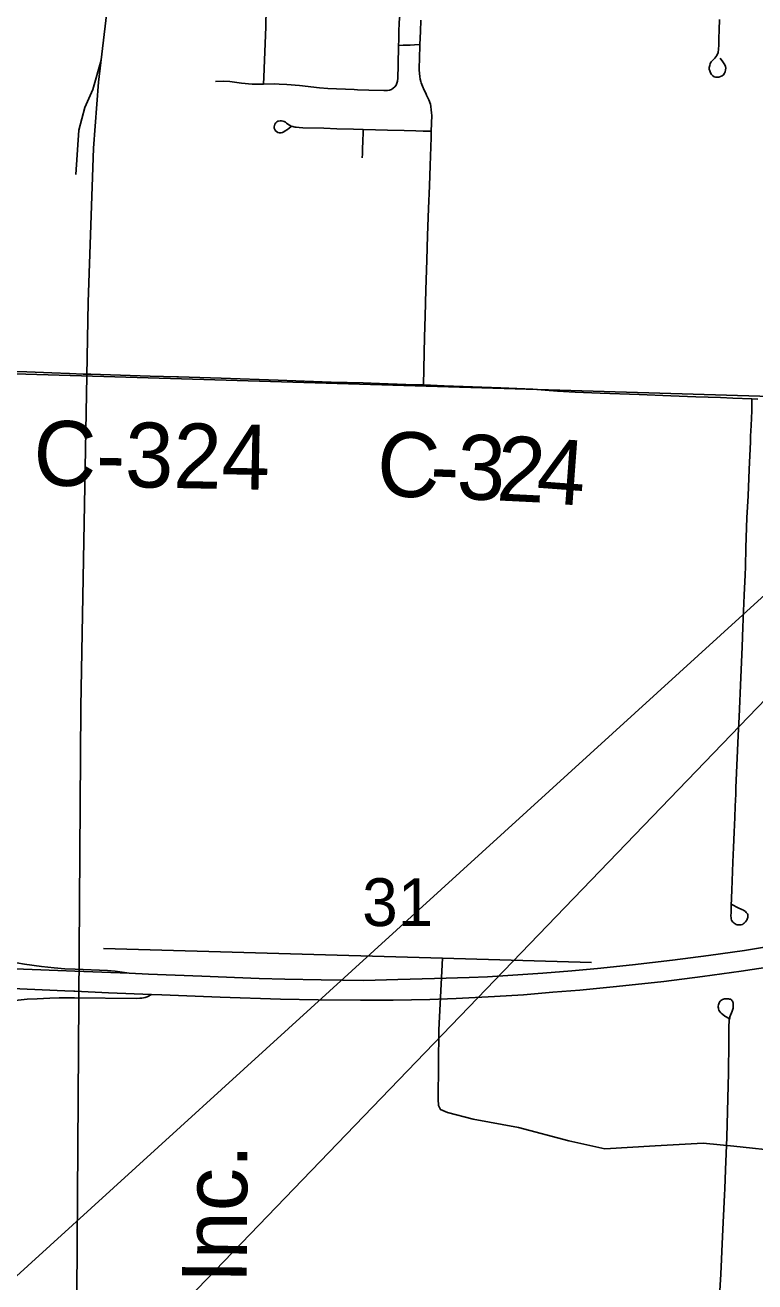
# Model space of a CAD drawing. Extents: x -59 to 43, y 0 to 22.
# Drawn here: x 25.359 to 25.998, y 15.494 to 16.594 of the extents above; entities that cross this region are included whole.
import ezdxf

# ---------------------------------------------------------------- set-up
doc = ezdxf.new("R2010")
doc.units = 0
for name, color, linetype in [('BR_P_Gen_Text', 7, 'Continuous'), ('GM_X_City_Street', 7, 'Continuous'), ('GM_X_County_Road', 7, 'Continuous'), ('GM_X_County_Road_Text', 7, 'Continuous'), ('GM_X_Interchange_Ramps', 7, 'Continuous'), ('GM_X_Minor_River', 7, 'Continuous'), ('GM_X_Rail_Line', 7, 'Continuous'), ('GM_X_Rail_Line_Text', 7, 'Continuous'), ('GM_X_Section', 7, 'Continuous'), ('GM_X_Section_Text', 7, 'Continuous'), ('GM_X_Township_Road', 7, 'Continuous'), ('GM_X_US_Route', 7, 'Continuous')]:
    doc.layers.add(name, color=color, linetype=linetype)

msp = doc.modelspace()

# ---------------------------------------------------------------- linework, layer by layer
at = {"layer": 'BR_P_Gen_Text'}
msp.add_lwpolyline([(26.7273, 16.7521), (23.5585, 13.8664), (23.9482, 13.8664)], close=True, dxfattribs=at)
at = {"layer": 'GM_X_City_Street'}
for points in [[(25.5677, 16.5426), (25.568, 16.5486), (25.5687, 16.5635), (25.5699, 16.5926), (25.5703, 16.6087), (25.5706, 16.6155), (25.5708, 16.6208)], [(25.5708, 16.6208), (25.5869, 16.6207), (25.5925, 16.6209), (25.6242, 16.6204), (25.6527, 16.6191), (25.6788, 16.6177), (25.6813, 16.6173), (25.6831, 16.6168), (25.6847, 16.6159), (25.6861, 16.6147), (25.6869, 16.6138), (25.6876, 16.6121), (25.6879, 16.6102), (25.6878, 16.6077), (25.6867, 16.5966), (25.6862, 16.5879), (25.6862, 16.581), (25.686, 16.5764)], [(25.7078, 16.2791), (25.7089, 16.321), (25.7093, 16.3394), (25.7099, 16.3623), (25.7108, 16.3884), (25.7114, 16.4101), (25.7124, 16.4336), (25.7132, 16.4534), (25.7138, 16.4714), (25.7145, 16.4957), (25.7147, 16.5012), (25.7151, 16.5149), (25.715, 16.5173), (25.7147, 16.52), (25.7144, 16.5228), (25.7139, 16.525), (25.7126, 16.5287), (25.7115, 16.5312), (25.7106, 16.5328), (25.7098, 16.5345), (25.7084, 16.5373), (25.7069, 16.5407), (25.7058, 16.5437), (25.7055, 16.5449), (25.705, 16.5468), (25.7046, 16.5493), (25.7043, 16.5518), (25.7042, 16.555), (25.7045, 16.5668), (25.7047, 16.5749), (25.7048, 16.5771), (25.7053, 16.5886), (25.7056, 16.5985)], [(25.9677, 16.5653), (25.97, 16.5621), (25.9717, 16.5593), (25.9723, 16.5578), (25.9725, 16.5564), (25.9723, 16.5549), (25.972, 16.5534), (25.9715, 16.5521), (25.9705, 16.5507), (25.9694, 16.5499), (25.968, 16.5491), (25.9664, 16.5486), (25.965, 16.5485), (25.9636, 16.5486), (25.9622, 16.549), (25.9611, 16.5499), (25.96, 16.551), (25.9591, 16.5524), (25.9584, 16.5541), (25.9581, 16.5556), (25.9581, 16.5571), (25.9584, 16.5588), (25.9588, 16.5606), (25.9597, 16.5619), (25.9606, 16.563), (25.9622, 16.5645), (25.963, 16.5653), (25.9638, 16.5663), (25.9648, 16.5677), (25.9658, 16.5702), (25.966, 16.5732), (25.9663, 16.5766), (25.9665, 16.5823), (25.9667, 16.59), (25.967, 16.5992)], [(25.5677, 16.5426), (25.5779, 16.5427), (25.5816, 16.5426), (25.5884, 16.5421), (25.5995, 16.5412), (25.6168, 16.5393), (25.6242, 16.5387), (25.6471, 16.5377), (25.6502, 16.5376), (25.6601, 16.5373), (25.6732, 16.5368), (25.6763, 16.5369), (25.6781, 16.5373), (25.6798, 16.5379), (25.6814, 16.5389), (25.6828, 16.5401), (25.6839, 16.5416), (25.6846, 16.5433), (25.6851, 16.5451), (25.6853, 16.5476), (25.6858, 16.5592), (25.686, 16.5764)], [(25.686, 16.5764), (25.69, 16.5766), (25.6923, 16.5766), (25.6963, 16.5767), (25.7, 16.5769), (25.7048, 16.5771)], [(25.5259, 16.5448), (25.5327, 16.545), (25.5383, 16.5447), (25.5487, 16.5434), (25.558, 16.5426), (25.5611, 16.5425), (25.5677, 16.5426)], [(25.5921, 16.5054), (25.5902, 16.504), (25.5888, 16.5029), (25.5869, 16.5015), (25.5856, 16.5007), (25.5845, 16.5002), (25.5833, 16.4999), (25.5821, 16.4998), (25.5815, 16.4999), (25.5803, 16.5002), (25.5792, 16.5009), (25.5787, 16.5013), (25.578, 16.5022), (25.5777, 16.5028), (25.5773, 16.504), (25.5772, 16.5052), (25.5774, 16.5064), (25.5778, 16.5075), (25.5785, 16.5085), (25.5794, 16.5094), (25.5805, 16.51), (25.5811, 16.5102), (25.5823, 16.5104), (25.5835, 16.5104), (25.5848, 16.5102), (25.5859, 16.5097), (25.587, 16.5091), (25.588, 16.5084), (25.59, 16.5069), (25.5911, 16.5063), (25.5922, 16.5058), (25.5934, 16.5054), (25.5945, 16.505), (25.5955, 16.5048), (25.5965, 16.5047), (25.599, 16.5045), (25.6023, 16.5043), (25.6208, 16.5038), (25.6319, 16.5035), (25.6465, 16.5031), (25.6551, 16.5029), (25.6658, 16.5026), (25.6763, 16.5023), (25.691, 16.5019), (25.7012, 16.5016), (25.7076, 16.5014), (25.7147, 16.5012)], [(25.6543, 16.478), (25.6544, 16.4816), (25.6545, 16.4852), (25.6548, 16.4931), (25.655, 16.4995), (25.6551, 16.5029)]]:
    msp.add_lwpolyline(points, dxfattribs=at)
at = {"layer": 'GM_X_County_Road'}
msp.add_line((25.9954, 16.2669), (26.0005, 16.2667), dxfattribs=at)
for points in [[(25.3268, 16.2917), (25.3358, 16.2915), (25.3513, 16.2908), (25.3606, 16.2905), (25.3825, 16.2897), (25.3981, 16.2891), (25.4099, 16.2886)], [(25.4099, 16.2886), (25.4123, 16.2886), (25.4157, 16.2885), (25.4166, 16.2885)], [(25.4166, 16.2885), (25.4251, 16.2883), (25.4686, 16.2869), (25.4919, 16.2863), (25.4927, 16.2862)], [(25.4927, 16.2862), (25.4935, 16.2862), (25.5308, 16.285), (25.5806, 16.2834), (25.6272, 16.2817), (25.6552, 16.2809), (25.6693, 16.2803)], [(25.6693, 16.2803), (25.6925, 16.2794), (25.7078, 16.2791)], [(25.7078, 16.2791), (25.726, 16.2784), (25.7508, 16.2774), (25.7757, 16.2766), (25.8036, 16.2754), (25.8252, 16.2738), (25.8407, 16.2728), (25.8625, 16.2719), (25.8966, 16.2707), (25.9245, 16.2697), (25.9463, 16.2688), (25.968, 16.2681), (25.9787, 16.2677), (25.9954, 16.2669)]]:
    msp.add_lwpolyline(points, dxfattribs=at)
at = {"layer": 'GM_X_Interchange_Ramps'}
for points in [[(25.403, 15.7676), (25.394, 15.768), (25.3847, 15.7687), (25.3735, 15.7699), (25.3587, 15.7721), (25.3519, 15.7732), (25.3447, 15.7745), (25.3313, 15.7774), (25.3192, 15.7804), (25.2976, 15.7862), (25.2598, 15.7967), (25.2166, 15.8085), (25.2017, 15.8126), (25.1893, 15.816), (25.1864, 15.8168), (25.1842, 15.8171), (25.1817, 15.8174), (25.1772, 15.8175)], [(25.4502, 15.7641), (25.4379, 15.7658), (25.4313, 15.7664), (25.403, 15.7676)], [(25.4024, 15.7425), (25.4564, 15.7421), (25.4597, 15.7422), (25.4612, 15.7423), (25.4629, 15.7426), (25.4644, 15.743), (25.4659, 15.7435), (25.4698, 15.7454)], [(25.175, 15.7029), (25.1761, 15.7029), (25.1798, 15.703), (25.1847, 15.7038), (25.1914, 15.7052), (25.212, 15.7101), (25.2357, 15.7154), (25.2587, 15.7208), (25.2859, 15.7273), (25.3108, 15.7331), (25.3272, 15.7365), (25.3413, 15.739), (25.3505, 15.7403), (25.3611, 15.7414), (25.3697, 15.7418), (25.3808, 15.7423), (25.389, 15.7426), (25.4024, 15.7425)]]:
    msp.add_lwpolyline(points, dxfattribs=at)
at = {"layer": 'GM_X_Minor_River'}
for points in [[(25.8549, 15.7735), (25.7244, 15.7773), (25.4277, 15.7858)], [(26.0665, 15.6035), (25.9796, 15.6128), (25.9527, 15.6152), (25.9106, 15.613), (25.8666, 15.6105), (25.8351, 15.6174), (25.7911, 15.629), (25.7513, 15.6363), (25.7289, 15.6421), (25.7229, 15.6447), (25.721, 15.6482), (25.7206, 15.6539), (25.7212, 15.7146), (25.7244, 15.7773)]]:
    msp.add_lwpolyline(points, dxfattribs=at)
at = {"layer": 'GM_X_Rail_Line'}
for points in [[(25.3948, 14.1), (25.3961, 14.2211), (25.3988, 14.6701), (25.4079, 15.9972), (25.4144, 16.3516), (25.419, 16.4865), (25.4235, 16.5443), (25.4371, 16.6599), (25.4762, 17.0572), (25.4837, 17.1373), (25.4914, 17.219), (25.4936, 17.2735), (25.4946, 17.3274), (25.4973, 17.5422), (25.5003, 17.9438), (25.5067, 18.4239), (25.5079, 18.556), (25.5143, 18.6352), (25.5252, 18.7035), (25.5418, 18.7744), (25.5673, 18.8657), (25.6145, 19.001)], [(25.4037, 16.4635), (25.4063, 16.5022), (25.4115, 16.5219), (25.4185, 16.5378), (25.4258, 16.5635)]]:
    msp.add_lwpolyline(points, dxfattribs=at)
at = {"layer": 'GM_X_Section'}
for points in [[(25.1878, 17.2935), (26.2782, 17.275), (26.2361, 16.2622), (25.1744, 16.294), (25.173, 16.308)], [(25.1744, 16.294), (26.2361, 16.2622), (26.1685, 15.2661), (25.1667, 15.3001)]]:
    msp.add_lwpolyline(points, close=True, dxfattribs=at)
at = {"layer": 'GM_X_Township_Road'}
for points in [[(25.9777, 15.8242), (25.9834, 15.8214), (25.9865, 15.82), (25.9874, 15.8196), (25.9882, 15.8191), (25.989, 15.8186), (25.9897, 15.818), (25.9904, 15.8174), (25.991, 15.8167), (25.9914, 15.816), (25.9917, 15.8154), (25.9919, 15.8146), (25.9919, 15.814), (25.9918, 15.8129), (25.9916, 15.8122), (25.9912, 15.8114), (25.9909, 15.8107), (25.9904, 15.8099), (25.9899, 15.8092), (25.9893, 15.8085), (25.9886, 15.8079), (25.9878, 15.8074), (25.987, 15.8069), (25.9861, 15.8066), (25.9852, 15.8065), (25.9842, 15.8064), (25.9833, 15.8065), (25.9824, 15.8066), (25.9815, 15.8069), (25.9806, 15.8073), (25.9799, 15.8078), (25.9792, 15.8084), (25.9785, 15.8091), (25.978, 15.8098), (25.9776, 15.8107), (25.9773, 15.8116), (25.9771, 15.8125), (25.977, 15.8143), (25.9771, 15.8174), (25.9773, 15.823), (25.9777, 15.8367), (25.9787, 15.8612), (25.9792, 15.8742), (25.9798, 15.8876), (25.9803, 15.9004), (25.9807, 15.9105), (25.9812, 15.9208), (25.9814, 15.9263), (25.9834, 15.9722), (25.9841, 15.9886), (25.9856, 16.0231), (25.9867, 16.0498), (25.9874, 16.0672), (25.9886, 16.0952), (25.9895, 16.1128), (25.9898, 16.12), (25.9901, 16.1368), (25.991, 16.1629), (25.992, 16.1821), (25.993, 16.2051), (25.994, 16.2293), (25.9942, 16.2343), (25.9946, 16.2436), (25.9952, 16.2566), (25.9953, 16.2622), (25.9954, 16.2669)], [(25.9671, 15.4814), (25.9681, 15.5007), (25.9696, 15.5336), (25.9714, 15.5702), (25.9716, 15.5752), (25.9722, 15.5919), (25.9734, 15.6205), (25.975, 15.677), (25.975, 15.6851), (25.9751, 15.6956), (25.9753, 15.7087), (25.9753, 15.718), (25.9755, 15.7217), (25.9756, 15.7232), (25.9757, 15.7241), (25.9759, 15.725), (25.9761, 15.7258), (25.9782, 15.731), (25.9789, 15.7334), (25.9791, 15.735), (25.9791, 15.7362), (25.9791, 15.7372), (25.9789, 15.7381), (25.9787, 15.7388), (25.9783, 15.7395), (25.9779, 15.7402), (25.9775, 15.7407), (25.9765, 15.7413), (25.9758, 15.7415), (25.975, 15.7417), (25.9742, 15.7418), (25.9733, 15.7418), (25.9724, 15.7417), (25.9714, 15.7416), (25.9706, 15.7414), (25.9697, 15.7411), (25.9688, 15.7406), (25.9683, 15.7401), (25.9677, 15.7396), (25.9671, 15.7389), (25.9666, 15.7381), (25.9663, 15.7373), (25.966, 15.7363), (25.9659, 15.7354), (25.9659, 15.7345), (25.966, 15.7336), (25.9662, 15.7328), (25.9665, 15.7319), (25.967, 15.731), (25.9677, 15.7301), (25.9686, 15.729), (25.9698, 15.7279), (25.9718, 15.7266), (25.9755, 15.7245)]]:
    msp.add_lwpolyline(points, dxfattribs=at)
at = {"layer": 'GM_X_US_Route'}
for points in [[(25.4028, 15.7659), (25.4262, 15.7651), (25.4502, 15.7641), (25.4672, 15.7634), (25.5138, 15.7615), (25.5641, 15.7595), (25.5864, 15.7589), (25.6183, 15.7584), (25.6558, 15.7578), (25.6853, 15.7587), (25.7176, 15.7595), (25.748, 15.7603), (25.7638, 15.7609), (25.7861, 15.7625), (25.8124, 15.7641), (25.8378, 15.7661), (25.8601, 15.7682), (25.8907, 15.7715), (25.9259, 15.7755), (25.9574, 15.7796), (25.9888, 15.7841), (26.0225, 15.7895)], [(25.1713, 15.7747), (25.1756, 15.7745), (25.1789, 15.7744), (25.2398, 15.7722), (25.3429, 15.7682), (25.3877, 15.7664), (25.4028, 15.7659)], [(25.4017, 15.7484), (25.4026, 15.7483), (25.4323, 15.747), (25.4698, 15.7454), (25.4789, 15.7451), (25.5298, 15.7431), (25.5826, 15.7414), (25.6156, 15.7407), (25.6528, 15.7404), (25.6814, 15.7406), (25.7133, 15.7412), (25.7365, 15.7419), (25.77, 15.7438), (25.7955, 15.7453), (25.8211, 15.7474), (25.8446, 15.7493), (25.8768, 15.7524), (25.9182, 15.7569), (25.9521, 15.7611), (25.986, 15.7659), (26.0112, 15.7697)], [(25.1701, 15.757), (25.171, 15.7569), (25.1754, 15.7567), (25.1931, 15.756), (25.2596, 15.7538), (25.3478, 15.7506), (25.3938, 15.7487), (25.4017, 15.7484)]]:
    msp.add_lwpolyline(points, dxfattribs=at)

# ---------------------------------------------------------------- texts
at = {"layer": 'GM_X_County_Road_Text'}
for s, height, rotation, p in [('C-324', 0.05682, 358.8957, (25.3661, 16.1913)), ('C', 0.0568, 357.8451, (25.6664, 16.1821)), ('3', 0.0568, 357.694, (25.7363, 16.1795)), ('2', 0.0568, 357.1628, (25.7711, 16.1781)), ('4', 0.0568, 355.7809, (25.8057, 16.1764)), ('-', 0.0568, 357.8139, (25.713, 16.1804))]:
    msp.add_text(s, height=height, rotation=rotation, dxfattribs=at).set_placement(p)
at = {"layer": 'GM_X_Rail_Line_Text'}
msp.add_text('Inc.', height=0.05663, rotation=89.6631, dxfattribs=at).set_placement((25.5531, 15.4924))
at = {"layer": 'GM_X_Section_Text'}
msp.add_text('31', height=0.04186, rotation=0, dxfattribs=at).set_placement((25.6542, 15.8054))

doc.saveas('drawing.dxf')
